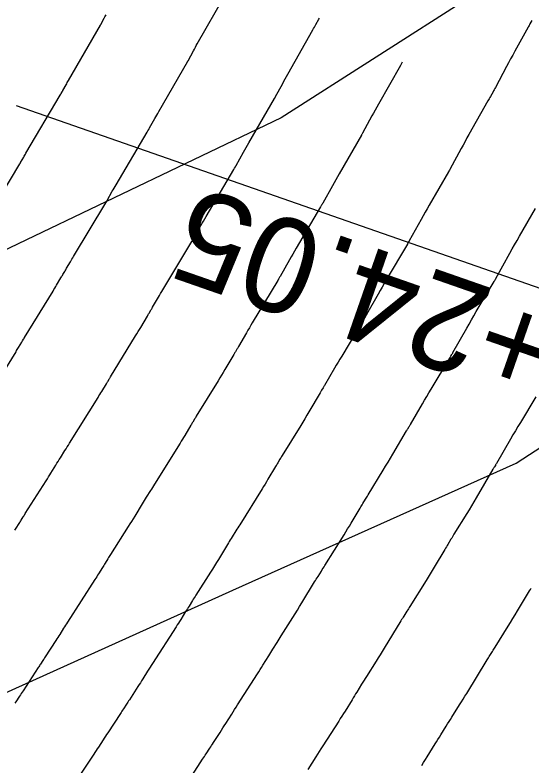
# Model space of a CAD drawing. Extents: x 1710723 to 1713003, y 548603 to 551142.
# Drawn here: x 1712264.87 to 1712297.4, y 549508.21 to 549555.47 of the extents above; entities that cross this region are included whole.
import ezdxf

# ---------------------------------------------------------------- set-up
doc = ezdxf.new("R2010")
doc.units = 0
for name, color, linetype in [('R_Contours', 7, 'Continuous'), ('R_Horz Alg', 7, 'Continuous'), ('R_Horz Alg Annot', 7, 'Continuous'), ('R_MOT', 7, 'Continuous')]:
    doc.layers.add(name, color=color, linetype=linetype)

msp = doc.modelspace()

# ---------------------------------------------------------------- linework, layer by layer
at = {"layer": 'R_Contours'}
for points in [[(1712262.942, 549531.057), (1712264.938, 549534.258), (1712264.978, 549534.322), (1712265.017, 549534.386), (1712265.056, 549534.451), (1712265.095, 549534.515), (1712265.298, 549534.854), (1712265.328, 549534.902), (1712265.357, 549534.951), (1712265.415, 549535.048), (1712265.429, 549535.073), (1712265.444, 549535.097), (1712265.458, 549535.121), (1712265.473, 549535.145), (1712267.273, 549538.077), (1712267.33, 549538.17), (1712267.386, 549538.263), (1712267.442, 549538.357), (1712267.497, 549538.45), (1712267.77, 549538.913), (1712267.8, 549538.964), (1712267.83, 549539.013), (1712267.86, 549539.063), (1712267.89, 549539.113), (1712268.01, 549539.312), (1712268.04, 549539.361), (1712268.07, 549539.411), (1712268.1, 549539.461), (1712268.129, 549539.512), (1712268.365, 549539.919), (1712268.414, 549540.003), (1712268.464, 549540.088), (1712268.514, 549540.172), (1712268.564, 549540.256), (1712270.6, 549543.642), (1712270.613, 549543.664), (1712270.626, 549543.686), (1712270.658, 549543.742), (1712270.677, 549543.776), (1712271.009, 549544.362), (1712271.067, 549544.463), (1712271.125, 549544.564), (1712271.184, 549544.665), (1712271.243, 549544.766), (1712273.197, 549548.081), (1712273.223, 549548.126), (1712273.25, 549548.171), (1712273.302, 549548.261), (1712273.315, 549548.284), (1712273.328, 549548.306), (1712273.341, 549548.329), (1712273.354, 549548.352), (1712273.688, 549548.953), (1712273.748, 549549.061), (1712273.809, 549549.168), (1712273.87, 549549.275), (1712273.931, 549549.382), (1712275.741, 549552.517), (1712275.751, 549552.534), (1712275.776, 549552.58), (1712275.78, 549552.586), (1712276.125, 549553.222), (1712276.184, 549553.329), (1712276.243, 549553.437), (1712276.303, 549553.544), (1712276.364, 549553.651), (1712278.132, 549556.775)], [(1712262.93, 549542.346), (1712265.18, 549546.089), (1712265.192, 549546.109), (1712265.219, 549546.156), (1712265.227, 549546.169), (1712265.426, 549546.52), (1712265.46, 549546.581), (1712265.495, 549546.641), (1712265.53, 549546.702), (1712265.566, 549546.762), (1712267.728, 549550.431), (1712267.757, 549550.479), (1712267.785, 549550.528), (1712267.842, 549550.625), (1712267.856, 549550.649), (1712267.87, 549550.674), (1712267.884, 549550.698), (1712267.897, 549550.723), (1712268.094, 549551.076), (1712268.131, 549551.144), (1712268.169, 549551.211), (1712268.207, 549551.277), (1712268.245, 549551.344), (1712270.256, 549554.825), (1712270.264, 549554.84), (1712270.28, 549554.869), (1712270.502, 549555.278), (1712270.54, 549555.347), (1712270.578, 549555.416), (1712270.617, 549555.485)], [(1712264.874, 549523.005), (1712264.916, 549523.071), (1712264.957, 549523.138), (1712265.142, 549523.434), (1712265.174, 549523.486), (1712265.206, 549523.537), (1712265.237, 549523.589), (1712265.269, 549523.64), (1712265.397, 549523.847), (1712265.428, 549523.898), (1712265.461, 549523.95), (1712265.493, 549524.001), (1712265.525, 549524.052), (1712266.84, 549526.125), (1712266.917, 549526.246), (1712266.993, 549526.368), (1712267.068, 549526.49), (1712267.143, 549526.612), (1712267.451, 549527.116), (1712267.521, 549527.231), (1712267.592, 549527.346), (1712267.663, 549527.461), (1712267.735, 549527.575), (1712268.022, 549528.031), (1712268.094, 549528.145), (1712268.165, 549528.259), (1712268.237, 549528.374), (1712268.308, 549528.488), (1712270.108, 549531.375), (1712270.166, 549531.468), (1712270.223, 549531.562), (1712270.28, 549531.655), (1712270.337, 549531.749), (1712270.633, 549532.242), (1712270.654, 549532.277), (1712270.675, 549532.313), (1712270.696, 549532.348), (1712270.718, 549532.384), (1712270.802, 549532.525), (1712270.823, 549532.561), (1712270.844, 549532.596), (1712270.866, 549532.631), (1712270.887, 549532.667), (1712272.475, 549535.254), (1712272.557, 549535.387), (1712272.637, 549535.52), (1712272.717, 549535.654), (1712272.797, 549535.788), (1712273.217, 549536.501), (1712273.244, 549536.547), (1712273.271, 549536.593), (1712273.299, 549536.639), (1712273.327, 549536.685), (1712273.438, 549536.868), (1712273.466, 549536.914), (1712273.493, 549536.96), (1712273.521, 549537.006), (1712273.548, 549537.053), (1712273.914, 549537.684), (1712273.984, 549537.805), (1712274.055, 549537.925), (1712274.126, 549538.045), (1712274.197, 549538.165), (1712276.019, 549541.195), (1712276.028, 549541.21), (1712276.037, 549541.226), (1712276.046, 549541.241), (1712276.056, 549541.257), (1712276.1, 549541.336), (1712276.118, 549541.367), (1712276.127, 549541.383), (1712276.593, 549542.204), (1712276.674, 549542.346), (1712276.755, 549542.487), (1712276.837, 549542.628), (1712276.92, 549542.769), (1712278.666, 549545.731), (1712278.69, 549545.773), (1712278.715, 549545.814), (1712278.763, 549545.897), (1712278.775, 549545.918), (1712278.787, 549545.939), (1712278.799, 549545.96), (1712278.811, 549545.981), (1712279.282, 549546.829), (1712279.365, 549546.978), (1712279.448, 549547.126), (1712279.532, 549547.273), (1712279.617, 549547.42), (1712281.227, 549550.209), (1712281.236, 549550.224), (1712281.245, 549550.24), (1712281.27, 549550.287), (1712281.279, 549550.303), (1712281.748, 549551.166), (1712281.828, 549551.312), (1712281.909, 549551.458), (1712281.99, 549551.603), (1712282.072, 549551.749), (1712283.649, 549554.535), (1712283.698, 549554.62), (1712283.746, 549554.706), (1712283.794, 549554.791), (1712283.842, 549554.877), (1712284.034, 549555.22), (1712284.062, 549555.27)], [(1712297.444, 549555.121), (1712297.334, 549554.911), (1712297.306, 549554.859), (1712297.278, 549554.806), (1712297.25, 549554.754), (1712297.221, 549554.702), (1712296.38, 549553.183), (1712296.248, 549552.943), (1712296.116, 549552.702), (1712295.986, 549552.461), (1712295.856, 549552.219), (1712295.159, 549550.91), (1712295.121, 549550.838), (1712295.082, 549550.766), (1712295.043, 549550.695), (1712295.003, 549550.624), (1712294.844, 549550.339), (1712294.804, 549550.268), (1712294.764, 549550.197), (1712294.724, 549550.126), (1712294.684, 549550.055), (1712293.488, 549547.943), (1712293.363, 549547.722), (1712293.239, 549547.499), (1712293.116, 549547.277), (1712292.994, 549547.053), (1712292.278, 549545.736), (1712292.258, 549545.7), (1712292.225, 549545.64), (1712292.212, 549545.617), (1712292.199, 549545.593), (1712290.988, 549543.497), (1712290.857, 549543.269), (1712290.727, 549543.041), (1712290.598, 549542.812), (1712290.47, 549542.582), (1712289.724, 549541.239), (1712289.714, 549541.222), (1712289.704, 549541.205), (1712289.695, 549541.187), (1712289.684, 549541.17), (1712289.634, 549541.083), (1712289.614, 549541.049), (1712289.604, 549541.032), (1712288.274, 549538.776), (1712288.144, 549538.555), (1712288.015, 549538.333), (1712287.887, 549538.11), (1712287.76, 549537.887), (1712287.028, 549536.596), (1712287, 549536.547), (1712286.972, 549536.497), (1712286.915, 549536.399), (1712286.901, 549536.374), (1712286.887, 549536.35), (1712286.872, 549536.325), (1712286.858, 549536.301), (1712285.465, 549533.984), (1712285.35, 549533.792), (1712285.236, 549533.601), (1712285.123, 549533.408), (1712285.011, 549533.216), (1712284.385, 549532.135), (1712284.363, 549532.096), (1712284.34, 549532.058), (1712284.317, 549532.02), (1712284.294, 549531.981), (1712284.201, 549531.828), (1712284.178, 549531.79), (1712284.155, 549531.752), (1712284.132, 549531.713), (1712284.109, 549531.675), (1712283.395, 549530.462), (1712283.268, 549530.248), (1712283.14, 549530.033), (1712283.011, 549529.82), (1712282.88, 549529.607), (1712281.716, 549527.71), (1712281.681, 549527.652), (1712281.646, 549527.595), (1712281.611, 549527.538), (1712281.577, 549527.48), (1712281.44, 549527.249), (1712281.405, 549527.192), (1712281.371, 549527.134), (1712281.336, 549527.076), (1712281.302, 549527.019), (1712280.82, 549526.217), (1712280.728, 549526.065), (1712280.635, 549525.912), (1712280.542, 549525.761), (1712280.448, 549525.609), (1712279.039, 549523.349), (1712278.98, 549523.254), (1712278.92, 549523.159), (1712278.861, 549523.064), (1712278.801, 549522.968), (1712278.561, 549522.588), (1712278.502, 549522.493), (1712278.442, 549522.397), (1712278.383, 549522.302), (1712278.324, 549522.206), (1712277.695, 549521.173), (1712277.57, 549520.969), (1712277.445, 549520.766), (1712277.318, 549520.563), (1712277.19, 549520.361), (1712276.278, 549518.923), (1712276.223, 549518.836), (1712276.168, 549518.75), (1712276.114, 549518.663), (1712276.06, 549518.575), (1712275.845, 549518.226), (1712275.791, 549518.139), (1712275.737, 549518.052), (1712275.683, 549517.965), (1712275.629, 549517.878), (1712275.317, 549517.376), (1712275.247, 549517.264), (1712275.176, 549517.151), (1712275.105, 549517.039), (1712275.034, 549516.928), (1712273.543, 549514.611), (1712273.466, 549514.49), (1712273.389, 549514.369), (1712273.312, 549514.248), (1712273.236, 549514.127), (1712272.931, 549513.642), (1712272.855, 549513.521), (1712272.778, 549513.4), (1712272.701, 549513.279), (1712272.623, 549513.159), (1712272.081, 549512.326), (1712272.034, 549512.254), (1712271.987, 549512.182), (1712271.941, 549512.11), (1712271.894, 549512.037), (1712271.706, 549511.749), (1712271.66, 549511.676), (1712271.613, 549511.604), (1712271.566, 549511.532), (1712271.519, 549511.46), (1712270.723, 549510.246), (1712270.649, 549510.133), (1712270.576, 549510.021), (1712270.502, 549509.908), (1712270.428, 549509.795), (1712270.134, 549509.345), (1712270.06, 549509.232), (1712269.986, 549509.119), (1712269.912, 549509.007), (1712269.838, 549508.895), (1712269.005, 549507.635)], [(1712289.277, 549552.491), (1712289.255, 549552.451), (1712289.211, 549552.373), (1712289.166, 549552.295), (1712287.78, 549549.846), (1712287.676, 549549.662), (1712287.574, 549549.479), (1712287.472, 549549.294), (1712287.371, 549549.11), (1712286.778, 549548.019), (1712286.757, 549547.98), (1712286.735, 549547.94), (1712286.724, 549547.92), (1712286.713, 549547.901), (1712285.302, 549545.459), (1712285.195, 549545.271), (1712285.088, 549545.083), (1712284.981, 549544.895), (1712284.876, 549544.706), (1712284.267, 549543.61), (1712284.257, 549543.591), (1712284.246, 549543.572), (1712284.235, 549543.553), (1712284.224, 549543.534), (1712284.179, 549543.457), (1712284.157, 549543.419), (1712284.135, 549543.381), (1712282.597, 549540.773), (1712282.491, 549540.592), (1712282.385, 549540.41), (1712282.28, 549540.228), (1712282.176, 549540.045), (1712281.578, 549538.989), (1712281.555, 549538.949), (1712281.532, 549538.909), (1712281.485, 549538.828), (1712281.474, 549538.808), (1712281.462, 549538.788), (1712281.45, 549538.768), (1712281.438, 549538.748), (1712279.831, 549536.074), (1712279.738, 549535.919), (1712279.645, 549535.763), (1712279.554, 549535.607), (1712279.462, 549535.45), (1712278.966, 549534.594), (1712278.942, 549534.551), (1712278.917, 549534.509), (1712278.891, 549534.467), (1712278.866, 549534.425), (1712278.764, 549534.257), (1712278.738, 549534.215), (1712278.713, 549534.172), (1712278.688, 549534.13), (1712278.663, 549534.088), (1712278.096, 549533.125), (1712277.992, 549532.951), (1712277.888, 549532.777), (1712277.784, 549532.603), (1712277.678, 549532.43), (1712276.302, 549530.188), (1712276.273, 549530.142), (1712276.245, 549530.096), (1712276.217, 549530.049), (1712276.189, 549530.003), (1712276.079, 549529.817), (1712276.051, 549529.77), (1712276.023, 549529.723), (1712275.995, 549529.677), (1712275.967, 549529.63), (1712275.579, 549528.983), (1712275.504, 549528.86), (1712275.429, 549528.737), (1712275.354, 549528.614), (1712275.278, 549528.492), (1712273.674, 549525.919), (1712273.608, 549525.814), (1712273.543, 549525.709), (1712273.477, 549525.604), (1712273.411, 549525.5), (1712273.148, 549525.081), (1712273.082, 549524.977), (1712273.017, 549524.872), (1712272.952, 549524.767), (1712272.888, 549524.661), (1712272.419, 549523.893), (1712272.319, 549523.729), (1712272.219, 549523.567), (1712272.117, 549523.405), (1712272.015, 549523.243), (1712270.901, 549521.488), (1712270.858, 549521.419), (1712270.814, 549521.35), (1712270.771, 549521.28), (1712270.728, 549521.211), (1712270.557, 549520.933), (1712270.514, 549520.864), (1712270.471, 549520.795), (1712270.428, 549520.725), (1712270.385, 549520.656), (1712270.137, 549520.257), (1712270.081, 549520.167), (1712270.025, 549520.078), (1712269.968, 549519.989), (1712269.912, 549519.9), (1712268.181, 549517.209), (1712268.12, 549517.114), (1712268.059, 549517.019), (1712267.999, 549516.923), (1712267.938, 549516.828), (1712267.698, 549516.445), (1712267.638, 549516.349), (1712267.577, 549516.254), (1712267.516, 549516.159), (1712267.455, 549516.064), (1712266.781, 549515.028), (1712266.744, 549514.971), (1712266.707, 549514.914), (1712266.67, 549514.857), (1712266.633, 549514.801), (1712266.486, 549514.573), (1712266.449, 549514.517), (1712266.412, 549514.46), (1712266.375, 549514.403), (1712266.338, 549514.347), (1712265.387, 549512.895), (1712265.329, 549512.807), (1712265.272, 549512.719), (1712265.214, 549512.63), (1712265.156, 549512.542), (1712264.926, 549512.189), (1712264.868, 549512.101)], [(1712276.059, 549507.597), (1712276.699, 549508.574), (1712276.756, 549508.661), (1712276.813, 549508.749), (1712276.87, 549508.836), (1712276.927, 549508.924), (1712277.154, 549509.274), (1712277.211, 549509.362), (1712277.268, 549509.449), (1712277.325, 549509.537), (1712277.381, 549509.624), (1712277.802, 549510.271), (1712277.891, 549510.409), (1712277.979, 549510.546), (1712278.067, 549510.684), (1712278.154, 549510.822), (1712278.534, 549511.427), (1712278.626, 549511.573), (1712278.719, 549511.72), (1712278.812, 549511.866), (1712278.906, 549512.012), (1712280.155, 549513.955), (1712280.242, 549514.09), (1712280.327, 549514.225), (1712280.412, 549514.36), (1712280.497, 549514.495), (1712280.873, 549515.099), (1712280.938, 549515.204), (1712281.003, 549515.309), (1712281.068, 549515.414), (1712281.133, 549515.519), (1712281.392, 549515.94), (1712281.457, 549516.045), (1712281.522, 549516.15), (1712281.588, 549516.254), (1712281.654, 549516.359), (1712282.385, 549517.51), (1712282.528, 549517.738), (1712282.671, 549517.965), (1712282.812, 549518.194), (1712282.952, 549518.423), (1712283.761, 549519.751), (1712283.814, 549519.837), (1712283.867, 549519.923), (1712283.921, 549520.009), (1712283.975, 549520.095), (1712284.19, 549520.437), (1712284.244, 549520.523), (1712284.298, 549520.608), (1712284.351, 549520.694), (1712284.405, 549520.78), (1712285.618, 549522.726), (1712285.73, 549522.907), (1712285.842, 549523.088), (1712285.952, 549523.269), (1712286.062, 549523.451), (1712286.636, 549524.407), (1712286.677, 549524.476), (1712286.718, 549524.545), (1712286.76, 549524.613), (1712286.801, 549524.682), (1712286.964, 549524.957), (1712287.005, 549525.026), (1712287.047, 549525.095), (1712287.088, 549525.163), (1712287.13, 549525.231), (1712288.083, 549526.784), (1712288.237, 549527.037), (1712288.391, 549527.29), (1712288.543, 549527.545), (1712288.694, 549527.8), (1712289.555, 549529.262), (1712289.576, 549529.297), (1712289.596, 549529.331), (1712289.617, 549529.366), (1712289.638, 549529.4), (1712289.722, 549529.538), (1712289.743, 549529.572), (1712289.763, 549529.607), (1712289.784, 549529.641), (1712289.804, 549529.676), (1712290.56, 549530.981), (1712290.693, 549531.21), (1712290.827, 549531.438), (1712290.962, 549531.666), (1712291.098, 549531.893), (1712292.277, 549533.854), (1712292.294, 549533.883), (1712292.311, 549533.911), (1712292.328, 549533.94), (1712292.345, 549533.97), (1712292.412, 549534.086), (1712292.428, 549534.115), (1712292.445, 549534.144), (1712292.462, 549534.174), (1712292.478, 549534.203), (1712293.344, 549535.729), (1712293.494, 549535.992), (1712293.645, 549536.256), (1712293.798, 549536.518), (1712293.951, 549536.78), (1712295.073, 549538.682), (1712295.091, 549538.713), (1712295.109, 549538.744), (1712295.145, 549538.806), (1712295.154, 549538.822), (1712295.163, 549538.837), (1712295.172, 549538.853), (1712295.181, 549538.869), (1712296.064, 549540.459), (1712296.215, 549540.729), (1712296.367, 549540.998), (1712296.52, 549541.267), (1712296.674, 549541.535), (1712297.684, 549543.285)], [(1712297.696, 549531.407), (1712296.732, 549529.803), (1712296.574, 549529.54), (1712296.418, 549529.276), (1712296.263, 549529.012), (1712296.109, 549528.747), (1712295.223, 549527.217), (1712295.205, 549527.187), (1712295.186, 549527.156), (1712295.168, 549527.125), (1712295.15, 549527.094), (1712295.075, 549526.972), (1712295.057, 549526.941), (1712295.038, 549526.911), (1712295.02, 549526.88), (1712295.002, 549526.849), (1712293.935, 549525.039), (1712293.789, 549524.792), (1712293.642, 549524.547), (1712293.494, 549524.302), (1712293.345, 549524.058), (1712292.544, 549522.753), (1712292.496, 549522.673), (1712292.447, 549522.594), (1712292.399, 549522.514), (1712292.352, 549522.435), (1712292.162, 549522.115), (1712292.114, 549522.035), (1712292.066, 549521.955), (1712292.018, 549521.876), (1712291.971, 549521.796), (1712291.304, 549520.685), (1712291.176, 549520.474), (1712291.048, 549520.263), (1712290.918, 549520.053), (1712290.788, 549519.843), (1712289.771, 549518.211), (1712289.723, 549518.134), (1712289.675, 549518.058), (1712289.627, 549517.982), (1712289.58, 549517.906), (1712289.388, 549517.601), (1712289.34, 549517.525), (1712289.293, 549517.449), (1712289.245, 549517.372), (1712289.198, 549517.295), (1712288.148, 549515.571), (1712288.023, 549515.367), (1712287.897, 549515.164), (1712287.771, 549514.962), (1712287.643, 549514.76), (1712287.03, 549513.794), (1712286.953, 549513.672), (1712286.876, 549513.55), (1712286.8, 549513.427), (1712286.724, 549513.304), (1712286.421, 549512.812), (1712286.345, 549512.689), (1712286.269, 549512.567), (1712286.193, 549512.444), (1712286.116, 549512.321), (1712285.677, 549511.614), (1712285.578, 549511.456), (1712285.478, 549511.298), (1712285.378, 549511.14), (1712285.277, 549510.983), (1712284.268, 549509.413), (1712284.158, 549509.242), (1712284.049, 549509.07), (1712283.94, 549508.898), (1712283.831, 549508.726), (1712283.336, 549507.938)], [(1712290.515, 549508.191), (1712290.63, 549508.371), (1712290.744, 549508.552), (1712290.857, 549508.734), (1712291.36, 549509.543), (1712291.447, 549509.683), (1712291.534, 549509.824), (1712291.622, 549509.965), (1712291.708, 549510.105), (1712292.056, 549510.669), (1712292.143, 549510.809), (1712292.23, 549510.95), (1712292.318, 549511.09), (1712292.407, 549511.229), (1712292.901, 549512.009), (1712293.013, 549512.186), (1712293.124, 549512.363), (1712293.234, 549512.541), (1712293.343, 549512.719), (1712294.635, 549514.84), (1712294.676, 549514.907), (1712294.718, 549514.974), (1712294.759, 549515.041), (1712294.801, 549515.108), (1712294.969, 549515.374), (1712295.011, 549515.441), (1712295.053, 549515.508), (1712295.095, 549515.575), (1712295.136, 549515.641), (1712295.958, 549516.96), (1712296.106, 549517.199), (1712296.254, 549517.438), (1712296.4, 549517.678), (1712296.545, 549517.919), (1712297.305, 549519.184), (1712297.36, 549519.275), (1712297.414, 549519.366)]]:
    msp.add_lwpolyline(points, dxfattribs=at)
at = {"layer": 'R_Horz Alg'}
msp.add_arc((1711777.174, 549719.88), 636.62, 271.078651, 340.773399, dxfattribs=at)
at = {"layer": 'R_Horz Alg Annot'}
msp.add_lwpolyline([(1712378.285, 549510.238), (1712264.978, 549549.754)], dxfattribs=at)
at = {"layer": 'R_MOT'}
for points in [[(1712382.442, 549637.216), (1712376.862, 549631.065), (1712365.876, 549618.953), (1712354.889, 549606.841), (1712343.902, 549594.73), (1712324.743, 549579.522), (1712305.585, 549564.314), (1712293.618, 549556.651), (1712281.651, 549548.989), (1712265.067, 549541.043), (1712248.483, 549533.098), (1712232.098, 549528.438), (1712215.714, 549523.777), (1712191.894, 549519.603), (1712168.074, 549515.429), (1712151.97, 549514.415), (1712135.867, 549513.401), (1712119.764, 549512.387)], [(1712242.17, 549505.086), (1712260.767, 549511.196), (1712278.612, 549519.22), (1712296.458, 549527.243), (1712308.699, 549535.181), (1712320.941, 549543.118), (1712331.564, 549551.539), (1712342.187, 549559.961), (1712352.809, 549568.382), (1712361.752, 549575.471)]]:
    msp.add_lwpolyline(points, dxfattribs=at)

# ---------------------------------------------------------------- texts
at = {"layer": 'R_Horz Alg Annot'}
msp.add_text('PT 23+24.05', height=6, rotation=160.7734, dxfattribs=at).set_placement((1712319.875, 549529.55))

doc.saveas('drawing.dxf')
